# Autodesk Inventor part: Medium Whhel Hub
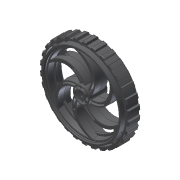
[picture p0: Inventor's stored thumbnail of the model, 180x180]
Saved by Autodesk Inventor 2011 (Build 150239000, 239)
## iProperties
Created: 2010-06
Part Number: Medium Whhel Hub
Document SubType Name: Modeling
Designer: Autodesk Inc.
Density: 1 g/cm^3
Catalog Web Link: http://www.vexrobotics.com/wheel-knobby-2pk.html
Vendor: Innovation First International, Inc.
Author: Autodesk Inc.
Title: Medium Whhel HUb
Subject: VEX Kit of Parts
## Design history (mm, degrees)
sketch "Sketch1"
  geometry: L1 (-37.749, -7)-(-38.314, -7); L2 (-40.994, -9.23)-(-41.138, -1); L3 (-38.677, -8.602)-(-39.512, -9.437); L4 (-39.724, -9.525)-(-40.695, -9.525); L5 (-4.539, 9.525)-(-4, 9.525); L6 (-4.878, 7)-(-4.839, 9.23); L7 (-7.372, 7)-(-4.878, 7); L8 (-8.289, 9.525)-(-7.711, 9.525); L9 (-8.75, 0)-(-8.589, 9.23); L10 (-4.839, -9.23)-(-4.878, -7); L11 (-4, -9.525)-(-4.539, -9.525); L12 (-7.372, -7)-(-7.411, -9.23); L13 (-7.711, -9.525)-(-8.289, -9.525); L14 (-8.589, -9.23)-(-8.75, 0); L15 (-4.878, -7)-(-7.372, -7); L16 (-1.613, 9.255)-(-1.613, -9.255); L17 (-41.138, -1)-(-42.858, -1); L18 (-42.858, -1)-(-42.95, -6.262); L19 (-42.95, -6.262)-(-43.45, -6.262); L20 (-43.45, -6.262)-(-44.45, -6.175); L21 (-7.411, 9.23)-(-7.372, 7); L22 (-36.818, -1.024)-(-36.794, -0.75); L23 (-44.45, 0)-(-36.794, 0); L24 (-44.45, -6.175)-(-44.45, 0); L25 (-36.794, -0.75)-(-36.794, 0); L26 (-37.749, 7)-(-38.313, 7); L27 (-39.724, 9.525)-(-40.694, 9.525); L28 (-38.677, 8.602)-(-39.512, 9.437); L29 (-44.45, 6.175)-(-44.45, 0); L30 (-40.994, 9.23)-(-41.138, 1); L31 (-43.45, 6.263)-(-44.45, 6.175); L32 (-42.858, 1)-(-42.95, 6.263); L33 (-42.95, 6.263)-(-43.45, 6.263); L34 (-36.794, 0.75)-(-36.794, 0); L35 (-36.818, 1.024)-(-36.794, 0.75); L36 (-41.138, 1)-(-42.858, 1); L37 (0, -13.601)-(0, 14.083); L38 (-1.613, 0)-(-8.75, 0); A1 r 22 centre (-16.603, -9.172) between (-38.513, -7.182) and (-38.589, -8.4); A2 r 0.3 centre (-38.889, -8.39) between (-38.677, -8.602) and (-38.589, -8.4); A3 r 0.3 centre (-40.694, -9.225) between (-40.994, -9.23) and (-40.695, -9.525); A4 r 0.3 centre (-39.724, -9.225) between (-39.724, -9.525) and (-39.512, -9.437); A5 r 25 centre (0, 34.203) between (-4, 9.525) and (-1.613, 9.255); A6 r 0.3 centre (-4.539, 9.225) between (-4.539, 9.525) and (-4.839, 9.23); A7 r 0.3 centre (-8.289, 9.225) between (-8.289, 9.525) and (-8.589, 9.23); A8 r 0.3 centre (-7.711, 9.225) between (-7.411, 9.23) and (-7.711, 9.525); A9 r 25 centre (0, -34.203) between (-1.613, -9.255) and (-4, -9.525); A10 r 0.3 centre (-4.539, -9.225) between (-4.839, -9.23) and (-4.539, -9.525); A11 r 0.3 centre (-7.711, -9.225) between (-7.711, -9.525) and (-7.411, -9.23); A12 r 0.3 centre (-8.289, -9.225) between (-8.589, -9.23) and (-8.289, -9.525); A13 r 22 centre (-16.603, 9.171) between (-38.589, 8.4) and (-38.513, 7.182); A14 r 0.3 centre (-38.889, 8.39) between (-38.589, 8.4) and (-38.677, 8.602); A15 r 0.3 centre (-39.724, 9.225) between (-39.512, 9.437) and (-39.724, 9.525); A16 r 0.3 centre (-40.694, 9.225) between (-40.694, 9.525) and (-40.994, 9.23); 4 further points
  constraints: 76 end point, 32 point on circle, 21 symmetric about line, 16 centre point, 4 perpendicular, 1 midpoint, 1 parallel, 21 other
revolve "Revolution1" stored, may be unused: angle "d0" = 90 deg
workplane "Work Plane1"
sketch "Sketch4"
  geometry: L1 (-46.89, 44.383)-(-47.611, 46.342); L2 (-51.595, 43.872)-(-51.312, 45.94); A1 r 46.45 centre (-44.45, 0) between (-47.611, 46.342) and (-51.312, 45.94); A2 r 46.45 centre (-44.45, 0) between (-47.611, 46.342) and (-51.312, 45.94); A3 r 44.279 centre (-44.469, 0.17) between (-46.89, 44.383) and (-51.595, 43.872); 2 further points; 1 other entity
  constraints: 6 point on circle, 4 end point, 3 centre point, 1 concentric, 1 other
extrude "Extrusion1" join sketch "Sketch4" stored distance "d1" = 25.4; taper "d2" = 0 deg
fillet "Fillet1" dims "d3" = 0.762
workplane "Work Plane2"
sketch "Sketch5"
  geometry: L1 (43.789, 13.035)-(2.02, -2.168); L2 (43.789, 13.035)-(88.239, 13.035); L3 (3.689, -2.351)-(5.525, -1.676); L4 (3.185, -0.967)-(5.021, -0.292); 6 further points; 4 other entities
  constraints: 8 end point, 1 equal length, 1 horizontal, 1 parallel, 10 other
  dimensions: "d8" = 160 deg angle of L1 L2; "d9" = 0.7366 distance from line of L1 L3.end; "d10" = 1.4732 distance between parallel lines of L4 L3
extrude "Extrusion2" join sketch "Sketch5" stored distance "d11" = 4.7625; taper "d12" = 0 deg
pattern_circular "Circular Pattern3" dims angle "d20" = 360 deg
workplane "Work Plane3"
mirror "Mirror1"
workplane "Work Plane4"
workplane "Work Plane5"
sketch "Sketch6"
  geometry: C1 r 8.75 at (0, 0) reference; C2 r 8.289 at (0, 0) reference; A1 r 38.24 centre (0.012, -0.013) between (-26.464, 27.579) and (-27.816, 26.215); A2 r 8.967 centre (1.327, -0.114) between (2.224, 8.808) and (1.31, 8.853); A3 r 8.921 centre (1.17, -0.38) between (5.636, 7.343) and (4.524, 7.887); A4 r 38.222 centre (0, 0) between (-25.914, 28.096) and (-28.214, 25.786); A5 r 8.591 centre (0, 0) between (0.946, 8.539) and (5.798, 6.34); 9 further points
  constraints: 10 point on circle, 5 centre point, 2 coincident, 1 concentric, 25 other
extrude "Extrusion3" join sketch "Sketch6" stored distance "d17" = 12.7; taper "d18" = 2 deg
sketch "Sketch7"
  geometry: A1 r 8.75 centre (-0.051, -0.113) between (4.748, 7.204) and (2.236, 8.333); A2 r 8.628 centre (0, 0) between (5.799, 6.389) and (0.946, 8.576) reference; 3 further points
  constraints: 4 point on circle, 1 centre point, 6 other
workplane "Work Plane7"
sketch "Sketch8"
  geometry: A1 r 8.75 centre (-0.051, -0.113) between (4.748, 7.204) and (2.236, 8.333) reference; A2 r 19.922 centre (-17.307, 9.021) between (2.599, 8.227) and (0.093, 18.723); A3 r 21.028 centre (-16.945, 7.736) between (4.083, 7.6) and (0.741, 19.111); A4 r 0.378 centre (0.423, 18.907) between (0.741, 19.111) and (0.093, 18.723); A5 r 8.923 centre (-0.118, -0.272) between (4.083, 7.6) and (2.599, 8.227); 3 further points
  constraints: 11 point on circle, 4 centre point, 2 tangent
loft "Loft1" sketch "Sketch8" dims "d25" = 0, "d26" = 90 deg, "d27" = 0, "d28" = 90 deg
fillet "Fillet6" dims "d33" = 0.254
fillet "Fillet7" dims "d34" = 0.254
mirror "Mirror3"
fillet "Fillet9" dims "d36" = 0.254
fillet "Fillet10" dims "d37" = 0.254
fillet "Fillet11" dims "d38" = 0.254
pattern_circular "Circular Pattern4" dims angle "d40" = 360 deg
sketch "Sketch9"
  geometry: L1 (19.098, 27.253)-(19.084, 27.212); L2 (-0.689, 22.352)-(-0.668, 22.316); L3 (-0.689, 22.352)-(-0.668, 22.316); A1 r 2.542 centre (0.602, 20.163) between (-0.689, 22.352) and (0.58, 17.621); A2 r 35.6 centre (17.416, -8.349) between (19.084, 27.212) and (-0.668, 22.316); A3 r 35.642 centre (17.416, -8.349) between (19.098, 27.253) and (-0.689, 22.352); A4 r 2.5 centre (0.602, 20.163) between (-0.668, 22.316) and (0.581, 17.663); A5 r 2.542 centre (0.602, 20.163) between (-0.689, 22.352) and (0.58, 17.621); A6 r 2.54 centre (31.526, 8.066) between (29.772, 6.229) and (33.986, 8.696); A7 r 35.082 centre (0, 0) between (33.986, 8.696) and (22.781, 26.678); A8 r 29.116 centre (8.986, -14.163) between (36.501, -4.638) and (29.73, 6.269); A9 r 36.795 centre (0, 0) between (34.456, 12.908) and (25.898, 26.137); A10 r 36.794 centre (0, 0) between (36.501, -4.638) and (34.456, 12.908); A11 r 30.744 centre (19.081, -3.842) between (25.898, 26.137) and (22.781, 26.678); 31 further points; 3 other entities
  constraints: 22 point on circle, 11 centre point, 6 end point, 1 tangent, 42 other
  dimensions: "d42" = 5.08 diameter of A6
extrude "Extrusion4" join sketch "Sketch9" stored distance "d43" = 2.54; taper "d44" = 0 deg
fillet "Fillet12" dims "d45" = 0.254
fillet "Fillet13" dims "d46" = 0.254
pattern_circular "Circular Pattern5" dims "d48" = 360 deg
workplane "Work Plane8"
sketch "Sketch10"
  geometry: A1 r 7.411 centre (-0.008, 0.004) between (7.182, -1.793) and (7.369, 0.71); A2 r 4.878 centre (-0.028, -0.229) between (4.828, -0.691) and (4.395, 1.827); A3 r 12.779 centre (0.614, -12.755) between (7.182, -1.793) and (4.828, -0.691); A4 r 15.065 centre (0.614, -12.755) between (7.369, 0.71) and (4.395, 1.827); 5 further points
  constraints: 8 point on circle, 4 centre point, 1 concentric, 2 other
  dimensions: "d70" = 2.286 radial gap between concentric circles of A4 A3
workplane "Work Plane9"
workplane "Work Plane10"
sketch "Sketch11"
  geometry: L1 (1.612, 0.952)-(1.558, 1.007); L2 (1.558, 1.025)-(1.612, 1.079); L3 (1.612, 1.104)-(1.612, 1.079); L4 (1.558, 1.177)-(1.612, 1.231); L5 (1.612, 1.362)-(1.612, 1.231); L6 (1.232, 1.612)-(1.177, 1.558); L7 (1.159, 1.558)-(1.105, 1.612); L8 (1.079, 1.612)-(1.105, 1.612); L9 (1.232, 1.612)-(1.362, 1.612); L10 (1.612, 0.952)-(1.612, -0.952); L11 (1.558, -1.007)-(1.612, -0.952); L12 (1.612, 1.104)-(1.558, 1.159); L13 (1.079, 1.612)-(1.025, 1.558); L14 (-1.362, 1.612)-(-1.231, 1.612); L15 (-1.177, 1.558)-(-1.231, 1.612); L16 (1.007, 1.558)-(0.952, 1.612); L17 (-0.952, 1.613)-(0.952, 1.612); L18 (-0.952, 1.613)-(-1.007, 1.558); L19 (-1.024, 1.558)-(-1.079, 1.612); L20 (-1.104, 1.613)-(-1.079, 1.612); L21 (-1.104, 1.613)-(-1.159, 1.558); L22 (1.613, -1.079)-(1.558, -1.024); L23 (1.613, -1.079)-(1.612, -1.105); L24 (1.558, -1.159)-(1.612, -1.105); L25 (1.613, -1.231)-(1.558, -1.177); L26 (1.613, -1.231)-(1.612, -1.362); L27 (1.362, -1.612)-(1.231, -1.612); L28 (1.177, -1.558)-(1.231, -1.612); L29 (1.104, -1.613)-(1.079, -1.612); L30 (1.024, -1.558)-(1.079, -1.612); L31 (0.952, -1.613)-(1.007, -1.558); L32 (0.952, -1.613)-(-0.952, -1.612); L33 (1.104, -1.613)-(1.159, -1.558); L34 (-1.007, -1.558)-(-0.952, -1.612); L35 (-1.079, -1.612)-(-1.025, -1.558); L36 (-1.079, -1.612)-(-1.105, -1.612); L37 (-1.159, -1.558)-(-1.105, -1.612); L38 (-1.232, -1.612)-(-1.177, -1.558); L39 (-1.612, -0.952)-(-1.558, -1.007); L40 (-1.558, -1.025)-(-1.612, -1.079); L41 (-1.612, -1.104)-(-1.612, -1.079); L42 (-1.612, -1.104)-(-1.558, -1.159); L43 (-1.558, -1.177)-(-1.612, -1.231); L44 (-1.612, -1.362)-(-1.612, -1.231); L45 (-1.232, -1.612)-(-1.362, -1.612); L46 (-1.612, -0.952)-(-1.612, 0.952); L47 (-1.558, 1.007)-(-1.612, 0.952); L48 (-1.613, 1.079)-(-1.558, 1.024); L49 (-1.613, 1.079)-(-1.612, 1.105); L50 (-1.558, 1.159)-(-1.612, 1.105); L51 (-1.613, 1.231)-(-1.558, 1.177); L52 (-1.613, 1.231)-(-1.612, 1.362); A1 r 0.013 centre (1.567, 1.016) between (1.558, 1.025) and (1.558, 1.007); A2 r 0.013 centre (1.567, 1.168) between (1.558, 1.177) and (1.558, 1.159); A3 r 0.25 centre (1.362, 1.362) between (1.612, 1.362) and (1.362, 1.612); A4 r 0.013 centre (1.168, 1.567) between (1.159, 1.558) and (1.177, 1.558); A5 r 0.012 centre (-1.016, 1.566) between (-1.024, 1.558) and (-1.007, 1.558); A6 r 0.012 centre (-1.168, 1.566) between (-1.177, 1.558) and (-1.159, 1.558); A7 r 0.013 centre (1.016, 1.567) between (1.007, 1.558) and (1.025, 1.558); A8 r 0.012 centre (1.566, -1.016) between (1.558, -1.007) and (1.558, -1.024); A9 r 0.013 centre (1.567, -1.168) between (1.558, -1.159) and (1.558, -1.177); A10 r 0.25 centre (1.362, -1.362) between (1.362, -1.612) and (1.612, -1.362); A11 r 0.012 centre (1.168, -1.566) between (1.177, -1.558) and (1.159, -1.558); A12 r 0.012 centre (1.016, -1.566) between (1.024, -1.558) and (1.007, -1.558); A13 r 0.013 centre (-1.016, -1.567) between (-1.007, -1.558) and (-1.025, -1.558); A14 r 0.013 centre (-1.168, -1.567) between (-1.159, -1.558) and (-1.177, -1.558); A15 r 0.013 centre (-1.567, -1.168) between (-1.558, -1.177) and (-1.558, -1.159); A16 r 0.013 centre (-1.567, -1.016) between (-1.558, -1.025) and (-1.558, -1.007); A17 r 0.25 centre (-1.362, -1.362) between (-1.612, -1.362) and (-1.362, -1.612); A18 r 0.25 centre (-1.362, 1.362) between (-1.362, 1.612) and (-1.612, 1.362); A19 r 0.013 centre (-1.567, 1.168) between (-1.558, 1.159) and (-1.558, 1.177); A20 r 0.012 centre (-1.566, 1.016) between (-1.558, 1.007) and (-1.558, 1.024); 1 further point
  constraints: 104 end point, 40 point on circle, 20 centre point
feature "iFeature2:1" sketch "Sketch11"
sketch "Sketch13"
  geometry: C1 r 4.878 at (0, 0) reference; A1 r 12.779 centre (0.614, -12.755) between (7.182, -1.793) and (4.828, -0.691) reference; A2 r 7.411 centre (-0.008, 0.004) between (7.182, -1.793) and (7.369, 0.71) reference; A3 r 15.065 centre (0.614, -12.755) between (7.369, 0.71) and (4.395, 1.827) reference; 1 further point
extrude "Extrusion7" cut sketch "Sketch10" stored distance "d64" = 25.4; taper "d65" = 0 deg
fillet "Fillet16" dims "d69" = 0.381
pattern_circular "Circular Pattern8" dims angle "d67" = 360 deg
sketch "Sketch14"
  geometry: A1 r 4.878 centre (0.642, 12.526) between (-3.781, 14.583) and (-4.214, 12.064) reference; 6 further points; 3 other entities
  constraints: 3 other
mirror "Mirror4"
pattern_circular "Circular Pattern9" dims angle "d72" = 360 deg
fillet "Fillet17" dims "d74" = 0.381
body "Solid1"
pattern_circular "Circular Pattern1" dims angle "d5" = 360 deg
node "Projected Loop1"
node "Projected Loop2"
node "Projected Loop3"
other parameters: "d7" = -1.27, "d16" = -2.54, "d23" = -6.2484, "d56" = -1.27, "d63" = -0.127
